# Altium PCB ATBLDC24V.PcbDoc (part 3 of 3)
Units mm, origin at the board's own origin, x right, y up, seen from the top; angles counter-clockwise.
Board outline 135 x 125 mm, 4 copper layers (Top Layer, GND, PWR/Signal, Bottom Layer), stack 1.716 mm thick; 340 components, 168 nets, 921 pads, 872 vias.
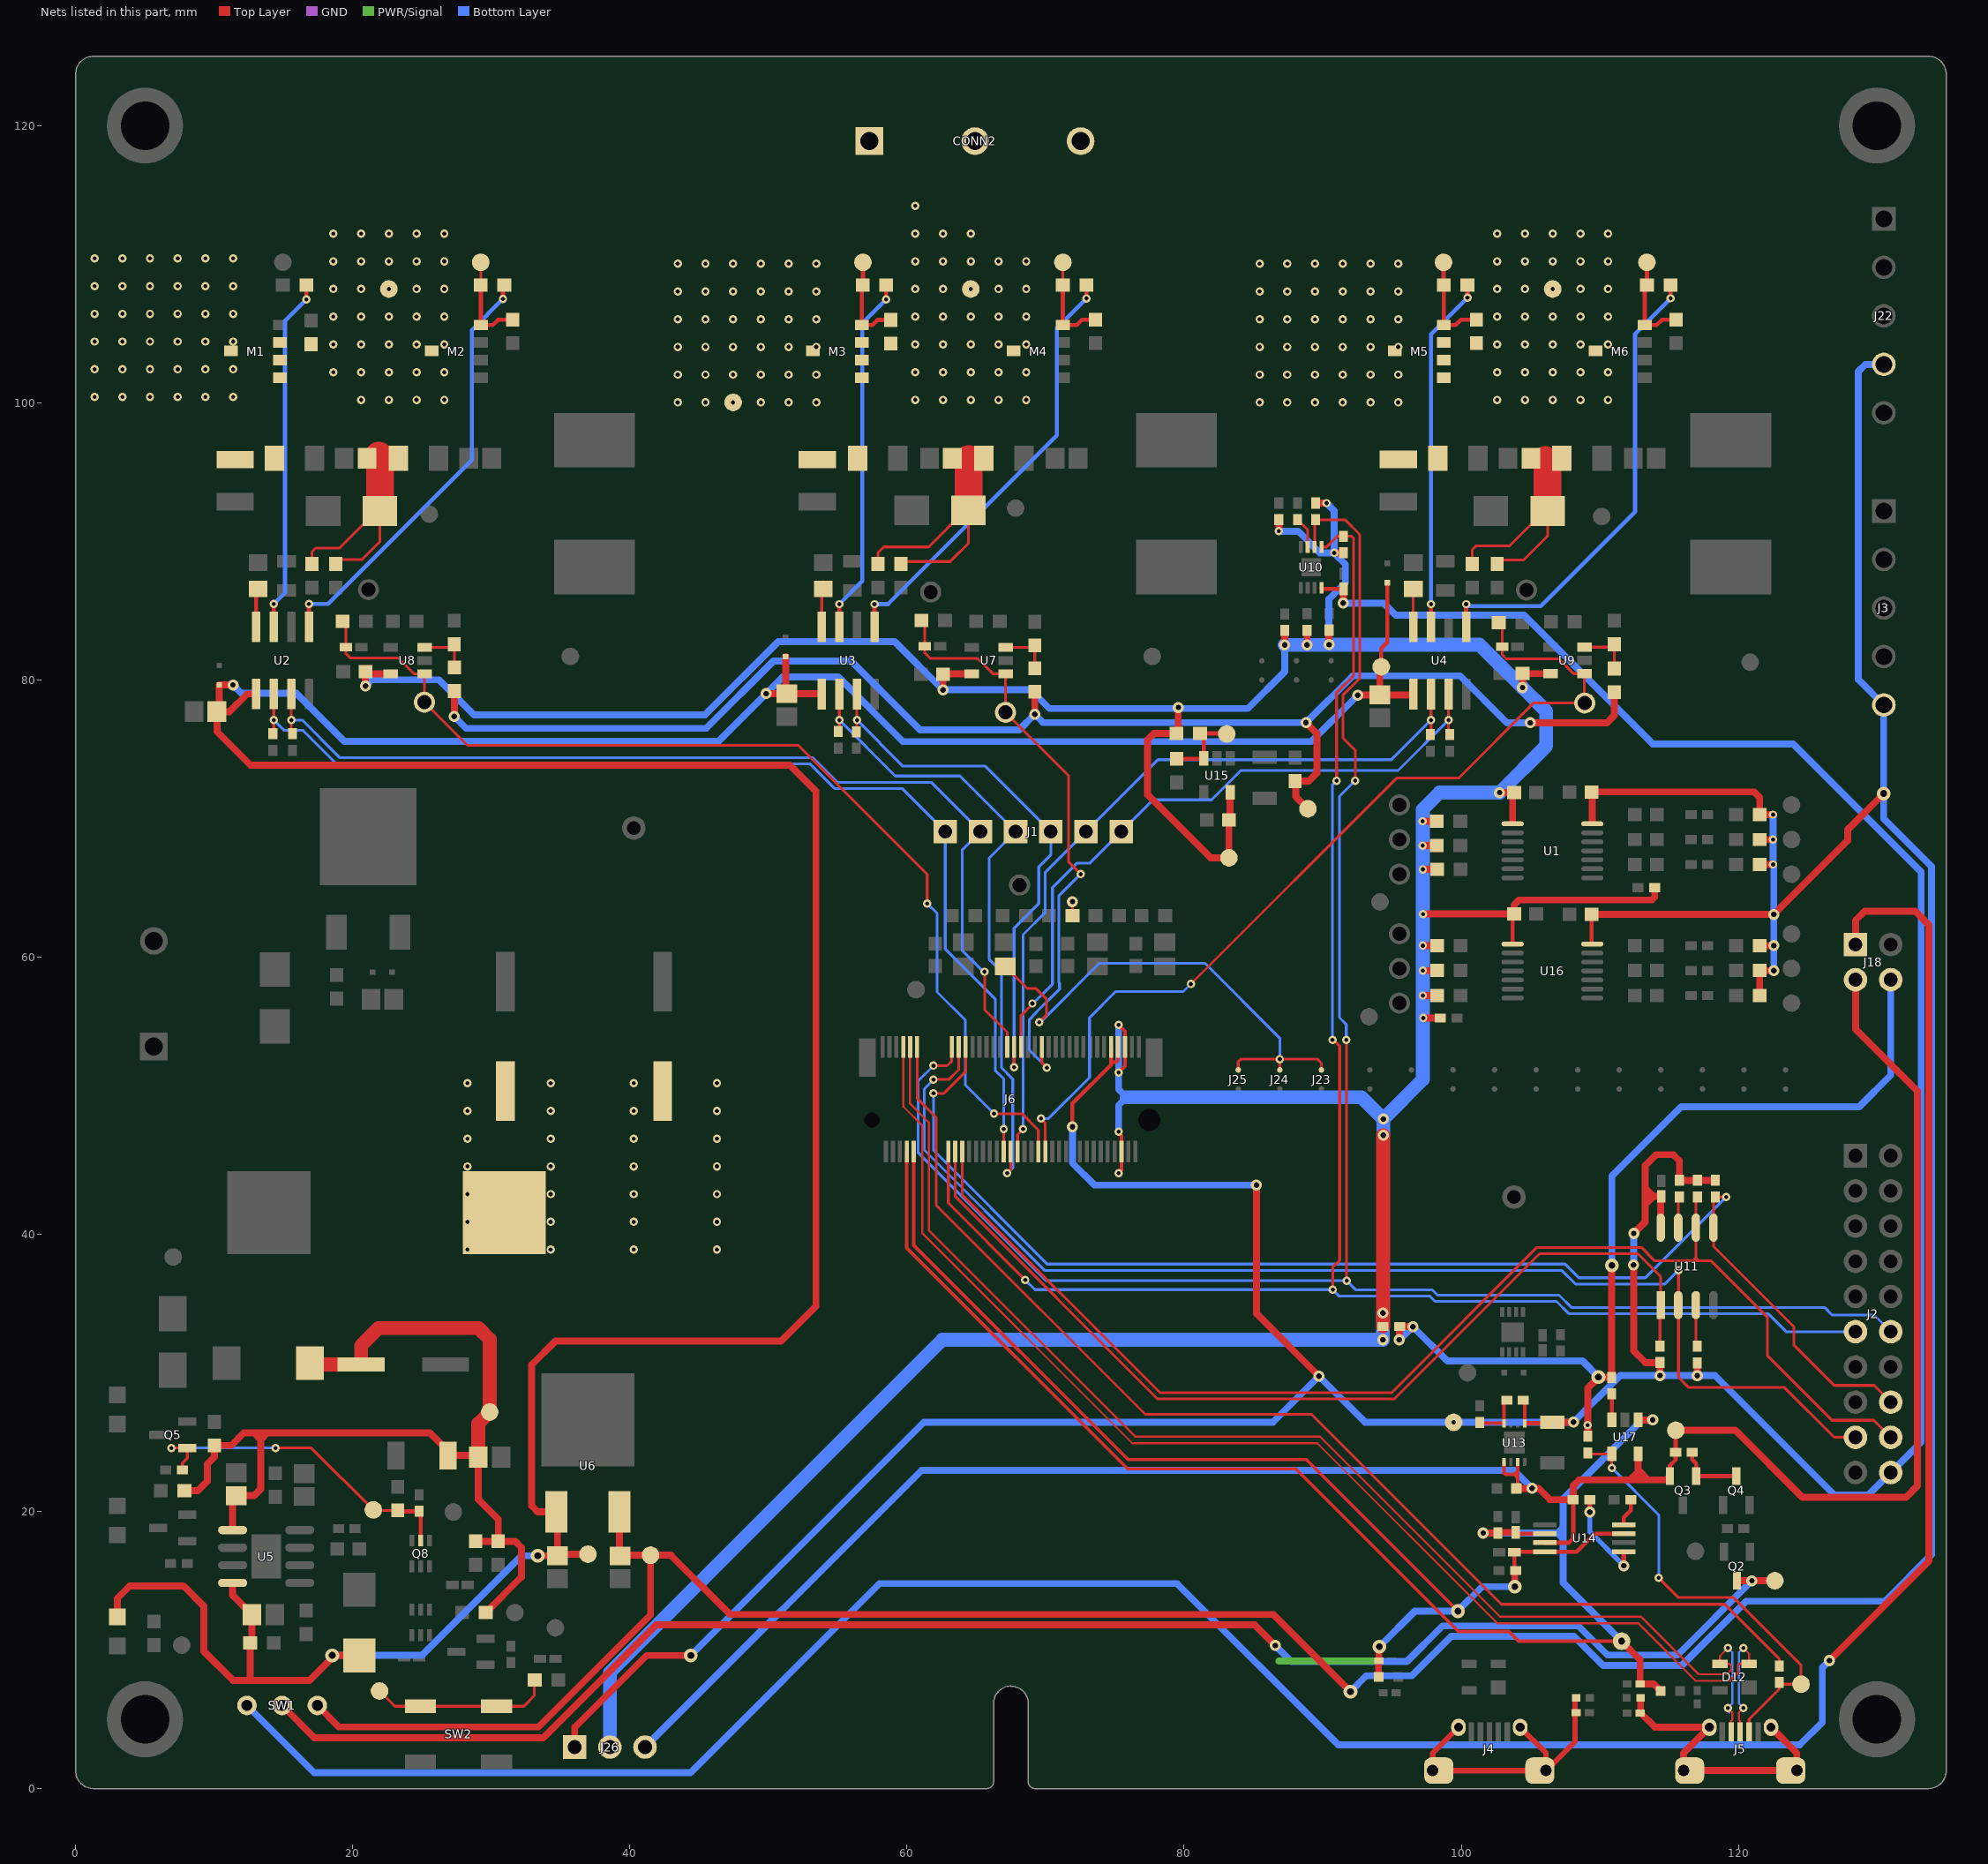
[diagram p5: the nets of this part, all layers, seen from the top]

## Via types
v1: diameter 0.6, hole 0.3, Top Layer to Bottom Layer, 769 vias
v2: diameter 0.8, hole 0.4, Top Layer to Bottom Layer, 92 vias
v3: diameter 1, hole 0.5, Top Layer to Bottom Layer, 11 vias

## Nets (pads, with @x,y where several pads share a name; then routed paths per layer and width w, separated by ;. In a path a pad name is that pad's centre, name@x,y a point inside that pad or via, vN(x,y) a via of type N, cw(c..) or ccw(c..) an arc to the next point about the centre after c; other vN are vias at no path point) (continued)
NetM2_2: M2.2 R11.2 R57.1 TP51.1 | length 7.1
  Top Layer w0.2: R57.1@29.235,108.5 TP51.1@29.235,110.135
  Top Layer w0.3: R57.1@29.55,108.5 29.25,108.2 M2.2@29.25,105.615 30.105,105.615 30.49,106 R11.2@31.55,106
NetM3_2: M3.2 R10.2 R17.2 TP8.1 | length 6.8
  Top Layer w0.3: TP8.1@56.8,110.087 56.817,110.103 56.817,108.517 R10.2@56.8,108.5 56.75,108.45 M3.2@56.75,105.615 57.519,105.615 57.884,105.98 R17.2@58.835,105.98
NetM4_2: M4.2 R21.2 R47.1 TP48.1 | length 7
  Top Layer w0.2: R47.1@71.25,108.5 TP48.1@71.25,110.135
  Top Layer w0.3: R47.1@71.25,108.5 M4.2@71.25,105.615 72.242,105.615 72.627,106 R21.2@73.6,106
NetM5_2: M5.2 R27.2 R58.2 TP9.1 | length 6.9
  Top Layer w0.3: TP9.1@98.724,110.017 98.724,108.526 R58.2@98.75,108.5 M5.2@98.75,105.615 99.593,105.615 99.978,106 R27.2@101.1,106
NetM6_2: M6.2 R31.2 R59.1 TP56.1 | length 7
  Top Layer w0.3: TP56.1@113.4,110.135 R59.1@113.4,108.5 113.25,108.35 M6.2@113.25,105.615 114.105,105.615 114.49,106 R31.2@115.5,106
NetQ3_1: Q3.1 Q4.3 R97.1 | length 4.7
  Top Layer w0.3: R97.1@116.675,24.267 116.675,23.756 116.962,23.469 Q3.1@116.962,22.549 119.849,22.549 Q4.3@119.85,22.55
NetQ5_1: Q5.1 Q8.5 R66.2 R117.1 R118.2 TP41.1 | length 24.8
  Top Layer w0.2: v1(6.904,24.579) Q5.1@8.05,24.579 8.05,23.84 7.7,23.49 R66.2@7.7,23 ; v1(14.416,24.579) 17.012,24.579 TP41.1@21.481,20.11 21.516,20.075 R117.1@23.243,20.075 R117.1@23.313,20.005
  Top Layer w0.3: R117.1@23.313,20.005 R118.2@24.797,20.005 24.9,19.901 Q8.5@24.9,17.896
  Bottom Layer w0.2: v1(6.904,24.579) v1(14.416,24.579)
NetR5_1: R5.1 U2.8 | length 2.7
  Top Layer w0.3: U2.8@13.023,83.837 R5.1@13.023,86.028 ; R5.1@13.165,86.593 R5.1@13.538,86.22
NetR10_1: R10.1 U3.7 | length 26.1
  Top Layer w0.3: U3.7@55.115,83.825 v1(55.115,85.47) ; v1(58.5,107.463) R10.1@58.5,108.5
  Bottom Layer w0.3: v1(55.115,85.47) 56.774,87.129 56.774,105.737 v1(58.5,107.463)
NetR15_1: R15.1 U3.8 | length 3.1
  Top Layer w0.2: U3.8@53.845,83.825 R15.1@53.845,86.794 ; R15.1@53.867,86.999 R15.1@53.95,87.081
NetR20_1: R20.1 U2.7 | length 25.6
  Top Layer w0.3: U2.7@14.293,83.837 v1(14.293,85.481) ; v1(16.65,107.462) R20.1@16.65,108.5
  Bottom Layer w0.3: v1(14.293,85.481) 15.11,86.299 15.11,105.922 v1(16.65,107.462)
NetR25_1: R25.1 U4.8 | length 2.7
  Top Layer w0.2: R25.1@96.539,86.527 96.539,83.831 U4.8@96.545,83.825
NetR39_2: R39.2 R44.2 U7.3 | length 3.8
  Top Layer w0.2: U7.3@67.125,82.353 69.083,82.353 R39.2@69.221,82.492 R44.2@69.221,80.842
NetR41_2: R41.2 R45.2 U8.3 | length 3.6
  Top Layer w0.2: U8.3@25.175,82.353 26.995,82.353 R41.2@27.06,82.418 ; R41.2@27.317,82.573 27.337,82.553 R45.2@27.337,80.898
NetR47_2: R47.2 U3.5 | length 31.6
  Top Layer w0.3: U3.5@57.655,83.825 v1(57.655,85.47) ; v1(72.95,107.532) R47.2@72.95,108.5
  Bottom Layer w0.3: v1(57.655,85.47) 58.634,85.47 70.819,97.654 70.819,105.401 v1(72.95,107.532)
NetR49_2: R49.2 R50.2 U9.3 | length 4
  Top Layer w0.2: U9.3@108.886,82.362 110.835,82.362 R49.2@111.043,82.569 111.052,82.56 R50.2@111.052,80.817
NetR54_1: R54.1 R56.2 TP61.1 U15.3 | length 5.8
  Top Layer w0.3: R56.2@79.473,74.309 81.393,74.309 U15.3@81.418,74.333 81.418,75.997 R54.1@81.276,76.139 ; R54.1@81.145,76.147 83.03,76.147 TP61.1@83.077,76.1
NetR57_2: R57.2 U2.5 | length 31.3
  Top Layer w0.3: U2.5@16.833,83.837 v1(16.833,85.481) ; v1(30.835,107.481) 30.835,108.4 R57.2@30.935,108.5
  Bottom Layer w0.3: v1(16.833,85.481) 18.2,85.481 28.592,95.872 28.592,105.238 v1(30.835,107.481)
NetR58_1: R58.1 U4.7 | length 25.8
  Top Layer w0.3: U4.7@97.815,83.825 v1(97.815,85.47) ; v1(100.45,107.581) R58.1@100.45,108.5
  Bottom Layer w0.3: v1(97.815,85.47) 97.815,104.946 v1(100.45,107.581)
NetR59_2: R59.2 U4.5 | length 34.1
  Top Layer w0.3: U4.5@100.355,83.825 v1(100.355,85.47) ; v1(115.1,107.536) R59.2@115.1,108.5
  Bottom Layer w0.3: v1(100.355,85.47) 100.494,85.33 105.741,85.33 112.546,92.136 112.546,104.982 v1(115.1,107.536)
NetR87_1: R87.1 U10.3 | length 2.3
  Top Layer w0.2: R87.1@88.187,91.562 88.917,90.833 U10.3@88.917,89.597
NetR89_2: R89.2 U11.3 | length 3
  Top Layer w0.2: U11.3@116.935,34.89 116.935,32.03 R89.2@117.035,31.93
NetR92_1: R92.1 U11.7 | length 2.2
  Top Layer w0.2: U11.7@115.665,40.478 115.665,42.61 R92.1@115.745,42.69
NetR94_1: R94.1 R96.2 U13.8 | length 3.5
  Top Layer w0.25: R94.1@101.334,26.417 101.384,26.367 U13.8@103.084,26.367 103.084,27.817 R96.2@103.284,28.017
NetR95_1: R95.1 U14.1 | length 6.8
  Top Layer w0.35: v2(109.284,19.945) R95.1@109.284,20.842 ; v2(111.734,16.083) U14.1@111.734,17.092
  Bottom Layer w0.35: v2(109.284,19.945) 109.284,18.533 v2(111.734,16.083)
NetR100_2: R100.2 U14.4 | length 2
  Top Layer w0.3: U14.4@111.734,19.042 111.734,19.567 112.234,20.067 R100.2@112.234,20.842
NetR102_2: R102.2 U17.3 | length 1.9
  Top Layer w0.3: R102.2@110.867,28.479 110.867,26.603 U17.3@110.869,26.601
NetR122_1: R122.1 SW2.1 SW2.2 TP44.1 | length 13.1
  Top Layer w0.2: TP44.1@21.93,7.046 23.035,5.941 SW2.1@24.885,5.941 SW2.2@30.385,5.941 32.34,5.941 33.1,6.701 33.1,7.81 R122.1@33.133,7.842
PA03_USB_ID: J6.11 R43.2 | length 86.9
  Top Layer w0.2: J6.11@60.73,53.525 60.73,49.813 62.111,48.432 62.111,42.093 77.199,27.005 89.191,27.005 102.901,13.296 119.026,13.296 122.95,9.371 R43.2@122.95,8.85
PWM_UH: J1.6 J6.28 R3.2 U2.2 | length 79.6
  Top Layer w0.2: R3.2@14.159,76.192 R3.2@14.226,76.125 14.293,76.192 v1(14.293,77.1) U2.2@14.293,78.987 ; J6.28@66.98,45.975 v1(66.98,47.586)
  Bottom Layer w0.2: v1(14.293,77.1) 15.023,76.37 16.384,76.37 18.804,73.95 52.991,73.95 54.775,72.166 59.642,72.166 J1.6@62.757,69.05 62.757,60.59 66.367,56.981 66.367,51.827 66.98,51.213 v1(66.98,47.586)
PWM_UL: J1.5 J6.29 R4.1 U2.3 | length 73.7
  Top Layer w0.2: U2.3@15.563,78.987 v1(15.563,77.1) 15.563,76.178 15.646,76.095 R4.1@15.743,76.192 ; v1(65.603,58.948) 65.603,56.208 67.23,54.58 J6.29@67.23,53.525
  Bottom Layer w0.2: v1(15.563,77.1) 16.347,77.1 19.047,74.4 53.177,74.4 54.961,72.616 61.732,72.616 J1.5@65.297,69.05 63.993,67.746 63.993,60.466 65.603,58.856 v1(65.603,58.948)
PWM_VH: J1.4 J6.30 R13.2 U3.2 | length 46.9
  Top Layer w0.2: R13.2@54.974,76.342 R13.2@55.035,76.281 55.115,76.361 v1(55.115,77.1) U3.2@55.115,78.975 ; v1(67.23,44.4) 67.48,44.651 J6.30@67.48,45.975
  Bottom Layer w0.2: v1(55.115,77.1) 59.15,73.066 63.822,73.066 J1.4@67.837,69.05 65.918,67.131 65.918,59.859 66.817,58.961 66.817,52.013 67.63,51.199 67.63,44.801 v1(67.23,44.4) ; v1@55.115,77.208 v1@55.169,77.154
PWM_VL: J1.3 J6.31 R14.1 U3.3 | length 39.7
  Top Layer w0.2: R14.1@56.343,76.263 R14.1@56.385,76.305 ; U3.3@56.385,78.975 v1(56.385,77.1) R14.1@56.385,76.305 ; R14.1@56.422,76.342 R14.1@56.385,76.305 ; v1@67.73,52.072 J6.31@67.73,53.525
  Bottom Layer w0.2: v1(56.385,77.1) 59.707,73.778 65.65,73.778 J1.3@70.377,69.05 70.377,67.375 69.511,66.509 69.511,63.872 67.73,62.091 v1(67.73,52.05)
PWM_WH: J1.2 J6.32 R23.2 U4.2 | length 56.5
  Top Layer w0.2: J6.32@67.98,45.975 67.98,47.192 68.377,47.589 v1(68.377,47.597) ; R23.2@97.689,76.142 R23.2@97.775,76.056 97.815,76.095 U4.2@97.815,78.975
  Bottom Layer w0.2: v1(68.377,47.597) 68.377,47.647 v1@68.38,47.65 ; v1@68.38,47.586 v1@68.38,47.65 ; v1(97.812,77.1) 94.961,74.25 78.117,74.25 J1.2@72.917,69.05 69.961,66.094 69.961,63.201 68.38,61.621 v1@68.38,47.65
PWM_WL: J1.1 J6.33 R24.1 U4.3 | length 49.1
  Top Layer w0.2: J6.33@68.23,53.525 68.23,55.78 69.05,56.6 v1(69.05,56.65) ; U4.3@99.085,78.975 v1(99.085,77.1) 99.085,76.146 R24.1@99.175,76.056 R24.1@99.262,76.142
  Bottom Layer w0.2: v1(69.05,56.65) 69.1,56.65 70.499,58.049 70.499,65.018 72.254,66.773 73.18,66.773 J1.1@75.457,69.05 77.757,71.35 81.98,71.35 84.092,73.462 95.447,73.462 v1(99.085,77.1)
REF_BEMF_SENS: J23.1 J24.1 J25.1 L5.2 | length 36.7
  Top Layer w0.2: L5.2@67.1,59.325 68.695,57.73 69.319,57.73 70.056,56.993 70.056,55.807 v1(69.55,55.3) ; J25.1@83.907,51.862 83.907,52.458 84.083,52.634 v1(86.907,52.634) ; J24.1@86.907,51.862 v1(86.907,52.634) ; J23.1@89.907,51.862 89.907,52.355 89.628,52.634 v1(86.907,52.634)
  Bottom Layer w0.2: v1(69.55,55.3) 69.628,55.3 73.881,59.553 81.505,59.553 86.907,54.151 v1(86.907,52.634)
SHIELD: C29.2 J4.6@97.943,1.3 J4.7@106.118,1.3 J4.8@99.805,4.425 J4.9@104.255,4.425 R37.2 | length 22.1
  Top Layer w0.4: J4.8@99.805,4.425 97.943,2.563 J4.6@97.943,1.3 J4.7@106.118,1.3 ; J4.9@104.255,4.425 106.118,2.563 J4.7@106.118,1.3 ; R37.2@108.22,6.547 108.22,3.402 J4.7@106.118,1.3
SPI_MISO: J2.17@128.46,25.349 J6.15 U11.2 | length 90.4
  Top Layer w0.2: v1@61.807,51.123 v1@61.912,51.123 ; v1(61.912,51.166) 63.021,51.166 63.73,51.876 J6.15@63.73,53.525 ; v1(115.68,37.4) 115.68,29.686 116.423,28.943 123.321,28.943 126.916,25.349 J2.17@128.46,25.349
  Bottom Layer w0.2: v1(61.912,51.166) 61.245,50.5 61.245,46.084 69.931,37.397 80.285,37.397 ; 80.285,37.397 81.569,37.397 ; 81.569,37.397 107.255,37.397 108.243,36.409 114.689,36.409 v1(115.68,37.4)
SPI_MOSI: J2.16@131,27.889 J6.17 R90.2 U11.5 | length 94.9
  Top Layer w0.2: v1(61.912,50.166) 62.658,50.166 64.23,51.739 J6.17@64.23,53.525 ; v1(119.12,42.69) R90.2@118.345,42.69 118.205,42.55 U11.5@118.205,40.478 118.205,39.14 124.003,33.342 124.003,32.014 126.928,29.089 129.8,29.089 J2.16@131,27.889
  Bottom Layer w0.2: v1(61.912,50.166) 61.912,46.053 70.118,37.847 80.471,37.847 ; 80.471,37.847 81.383,37.847 ; 81.383,37.847 107.488,37.847 108.477,36.859 113.288,36.859 v1(119.12,42.69)
SPI_SCK: J2.18@131,25.349 J6.16 R91.2 U11.6 | length 94.7
  Top Layer w0.2: J6.16@63.98,45.975 63.98,42.856 78.266,28.571 94.988,28.571 105.467,39.05 113.007,39.05 113.974,38.083 116.727,38.083 ; U11.6@116.95,39.721 U11.6@116.95,41.148 ; R91.2@117.045,42.69 116.935,42.58 U11.6@116.935,40.478 116.935,38.291 ; 117.491,38.083 117.143,38.083 ; J2.18@131,25.349 129.769,26.58 126.757,26.58 122.089,31.249 122.089,34.038 118.044,38.083 117.143,38.083 ; 116.727,38.083 116.938,38.083 ; 116.727,38.083 116.935,38.291 ; 116.935,38.291 117.143,38.083 ; 116.935,38.291 116.935,38.086 116.938,38.083 ; 116.938,38.083 117.143,38.083
SPI_SS: J6.14 R88.2 U11.1 | length 70.3
  Top Layer w0.2: J6.14@63.48,45.975 63.48,42.72 78.08,28.121 95.18,28.121 105.659,38.6 112.747,38.6 114.395,36.952 U11.1@114.395,34.89 114.345,34.84 R88.2@114.345,31.94 R88.2@114.365,31.94
TARGET_USB_HS_N: D12.3 J5.2 J6.9 | length 93.9
  Top Layer w0.15: J6.9@60.23,53.525 60.22,53.515 60.22,49.42 61.574,48.066 61.574,40.292 76.459,25.407 89.798,25.407 102.789,12.416 112.966,12.416 117.128,8.254 119.184,8.254 119.485,8.555 119.485,8.877 119.364,8.998 D12.3@119.02,8.998 ; D12.3@118.675,8.997 118.675,9.577 v1(119.246,10.148) ; v1(119.246,5.822) 119.565,5.503 119.565,4.941 119.48,4.856 J5.2@119.48,4.1
  GND w0.15: 119.34,5.493 v1@119.34,5.624
  Bottom Layer w0.15: v1(119.246,5.822) 119.565,6.142 119.565,9.828 v1(119.246,10.148)
TARGET_USB_HS_P: D12.2 J5.3 J6.7 | length 95.7
  Top Layer w0.15: J6.7@59.73,53.525 59.73,53.091 59.74,53.081 59.74,49.221 61.094,47.867 61.094,40.093 76.26,24.927 89.599,24.927 102.59,11.936 112.767,11.936 116.929,7.774 119.383,7.774 119.965,8.356 119.965,8.877 120.086,8.998 120.775,8.998 120.775,9.738 v1(120.365,10.148) ; J5.3@120.13,4.1 120.13,4.856 120.045,4.941 120.045,5.503 v1(120.365,5.822)
  Bottom Layer w0.15: v1(120.365,5.822) 120.045,6.142 120.045,9.828 v1(120.365,10.148)
TARGET_USB_ID: J5.4 R43.1 R104.1 TP68.1 U17.4 | length 32.4
  Top Layer w0.2: R104.1@109.131,24.228 109.209,24.151 U17.4@110.869,24.151 v1(110.869,23.136) ; v1(114.255,15.217) 115.684,13.787 119.653,13.787 124.525,8.916 TP68.1@124.525,7.531 R43.1@122.95,7.531 ; J5.4@120.78,4.1 120.78,5 122.95,7.17 R43.1@122.95,7.531 ; R43.1@122.95,7.65 R43.1@122.95,7.531
  Bottom Layer w0.2: v1(110.869,23.136) 114.255,19.751 v1(114.255,15.217)
TARGET_USB_SHIELD: C32.2 J5.6@116.043,1.3 J5.7@124.218,1.3 J5.8@117.905,4.425 J5.9@122.355,4.425 R42.2 | length 22.4
  Top Layer w0.5: R42.2@112.939,6.547 112.939,5.472 113.986,4.425 J5.8@117.905,4.425 116.043,2.563 J5.6@116.043,1.3 J5.7@124.218,1.3 124.218,2.563 J5.9@122.355,4.425
TWI_SCL: J2.12@131,32.969 J6.13 R84.2 U10.2 | length 145.8
  Top Layer w0.2: v1(61.912,52.166) 62.905,52.166 63.23,52.492 J6.13@63.23,53.525 ; U10.2@89.417,89.597 89.417,91.492 R84.2@89.487,91.562 91.615,91.562 92.677,90.5 92.677,80.112 91.458,78.892 91.458,75.818 92.35,74.926 v1(92.35,72.73) ; v1(91.707,54.023) 91.727,54.003 v1(91.727,36.65)
  Bottom Layer w0.2: v1(61.912,52.166) 60.795,51.05 60.795,45.897 70.043,36.65 v1(91.727,36.65) 92.395,35.982 97.929,35.982 98.302,35.608 107.064,35.608 107.949,34.724 126.213,34.724 126.768,34.169 129.8,34.169 J2.12@131,32.969 ; v1(91.707,54.023) 91.707,55.135 91.211,55.631 91.211,71.591 v1(92.35,72.73)
TWI_SDA: J2.11@128.46,32.969 J6.12 R83.2 U10.1 | length 131.1
  Top Layer w0.2: J6.12@62.98,45.975 62.98,42.26 v1(68.532,36.708) ; U10.1@89.917,89.597 90.28,89.597 91.05,90.368 R83.2@91.494,90.368 92.088,90.368 92.227,90.228 92.227,80.302 91,79.075 v1(91,72.73) ; v1(90.707,54.023) 90.788,54.023 91.223,53.588 91.223,38.114 90.727,37.618 v1(90.727,36)
  Bottom Layer w0.2: v1(68.532,36.708) 69.241,36 v1(90.727,36) 91.195,35.532 97.742,35.532 98.116,35.158 106.878,35.158 107.762,34.274 122.141,34.274 123.446,32.969 J2.11@128.46,32.969 ; v1(90.707,54.023) 90.707,72.437 v1(91,72.73)
U_EMF: C6.2 CONN2.1 D2.1 M1.1 M2.3 R7.1 R8.2 R9.2 R64.1 TP47.1 | length 17.5
  Top Layer w0.2: R8.2@17.049,88.403 17.049,89.236 17.328,89.516 19.036,89.516 21.709,92.188 D2.1@21.957,92.188 21.957,89.972 20.678,88.692 19.09,88.692 R64.1@18.962,88.564 ; R64.1@18.54,88.564 R64.1@18.962,88.564 ; R64.1@18.765,88.368 R64.1@18.962,88.564
  Top Layer w2: 21.884,96.191 21.957,96.117 D2.1@21.957,92.188
  other v1: 20.6,100.208 22.6,100.208 24.6,100.208 26.6,100.208 18.6,102.208 20.6,102.208 22.6,102.208 24.6,102.208 26.6,102.208 18.6,104.208 20.6,104.208 22.6,104.208 24.6,104.208 26.6,104.208 18.6,106.208 20.6,106.208 22.6,106.208 24.6,106.208 26.6,106.208 18.6,108.208 20.6,108.208 22.6,108.208 24.6,108.208 26.6,108.208 18.6,110.208 20.6,110.208 22.6,110.208 24.6,110.208 26.6,110.208 18.6,112.208 20.6,112.208 22.6,112.208 24.6,112.208 26.6,112.208
USHUNT_ADC: C34.2 J6.38 R52.2 TP13.1 U8.1 | length 76.7
  Top Layer w0.2: R52.2@19.259,84.233 19.51,83.983 C34.2@19.51,82.358 19.51,81.882 19.802,81.59 23.261,81.59 24.403,80.447 U8.1@25.175,80.447 25.175,78.398 TP13.1@25.168,78.39 28.277,75.281 52.155,75.281 61.456,65.981 v1@61.456,63.858 ; v1(66.277,48.7) 68.297,48.7 69.48,47.516 J6.38@69.48,45.975
  Bottom Layer w0.2: v1(61.457,63.87) 62.172,63.155 62.172,57.484 64.215,55.441 64.215,50.762 v1(66.277,48.7)
V_EMF: C11.2 CONN2.2 D4.1 M3.1 M4.3 R17.1 R18.2 R19.2 R68.1 TP46.1 | length 20.2
  Top Layer w0.2: R18.2@57.9,88.368 57.9,89.174 58.319,89.593 61.563,89.593 64.202,92.231 D4.1@64.435,92.231 64.435,89.86 63.118,88.542 59.724,88.542 R68.1@59.55,88.368
  Top Layer w2: D4.1@64.435,92.231 64.435,95.922 64.446,95.933
  other v1: 60.6,100.208 62.6,100.208 64.6,100.208 66.6,100.208 68.6,100.208 60.6,102.208 62.6,102.208 64.6,102.208 66.6,102.208 68.6,102.208 60.6,104.208 62.6,104.208 64.6,104.208 66.6,104.208 68.6,104.208 60.6,106.208 62.6,106.208 64.6,106.208 66.6,106.208 68.6,106.208 60.6,108.208 62.6,108.208 64.6,108.208 66.6,108.208 68.6,108.208 60.6,110.208 62.6,110.208 64.6,110.208 66.6,110.208 68.6,110.208 60.6,112.208 62.6,112.208 64.6,112.208 60.6,114.208
VCC_D: C4.1 C9.1 C14.1 C19.1 C22.1 C27.1 D1.2 D3.2 D5.2 D11.2 R32.2 TP10.1 TP39.1 U2.1 U3.1 U4.1 U5.8 U6.1 | length 288.2
  Top Layer w0.3: TP39.1@94.127,80.85 TP39.1@94.127,80.95 ; TP39.1@94.227,80.95 94.227,82.265 94.671,82.709 D5.2@94.671,87.009
  Top Layer w0.5: D11.2@3,12.4 3,13.722 3.908,14.63 7.689,14.63 7.719,14.6 7.812,14.6 9.254,13.158 9.254,9.909 11.361,7.802 12.482,7.802 ; U5.8@11.325,14.845 11.325,13.95 C19.1@12.725,12.55 12.725,10.661 R32.2@12.586,10.522 12.586,7.907 12.482,7.802 ; v2(11.354,79.638) D1.2@10.357,79.638 10.357,77.874 C4.1@10.192,77.709 ; U2.1@13.023,78.987 12.379,78.987 11.101,77.709 C4.1@10.192,77.709 ; v3@18.599,9.529 16.872,7.802 12.482,7.802 ; v3@18.68,9.61 C22.1@20.47,9.61 ; v3(33.35,16.801) C27.1@34.767,16.801 ; TP10.1@36.973,16.918 34.883,16.918 C27.1@34.767,16.801 ; v2(49.829,79.008) C9.1@51.338,79.008 ; D3.2@51.238,81.683 51.238,79.108 C9.1@51.338,79.008 ; U3.1@53.845,78.975 53.812,79.008 C9.1@51.338,79.008 ; v2(92.527,78.9) C14.1@93.845,78.9 ; C14.1@94.127,78.9 96.47,78.9 U4.1@96.545,78.975 ; C14.1@94.127,78.925 TP39.1@94.127,80.85 ; C4.1@10.192,77.709 10.192,76.28 12.617,73.856 51.541,73.856 53.427,71.97 53.427,34.812 50.912,32.297 34.622,32.297 32.917,30.593 32.917,20.396 33.351,19.962 U6.1@34.689,19.962 34.767,19.884 C27.1@34.767,16.801
  Bottom Layer w0.5: v2(11.354,79.638) 11.962,79.03 15.933,79.03 19.393,75.57 46.39,75.57 v2(49.829,79.008) 51.032,80.212 55.047,80.212 59.708,75.55 89.177,75.55 v2(92.527,78.9) ; v3(18.517,9.61) 24.981,9.61 32.172,16.801 v3(33.35,16.801)
VCC_D_P5V0: C1.1 C28.1 C44.1 J3.5 J22.4 R67.2 R70.2 R72.2 R109.2 R110.2 R111.2 SW1.2 TP11.1 U1.14 U6.3 U16.14 | length 290.8
  Top Layer w0.3: C44.1@109.416,63.081 109.416,60.99 U16.14@109.461,60.946
  Top Layer w0.5: SW1.2@17.44,6 18.992,4.448 33.396,4.448 41.49,12.543 TP11.1@41.49,16.842 ; U6.3@39.249,19.962 39.249,16.824 39.267,16.842 TP11.1@41.49,16.842 ; v3(92.002,6.995) 86.433,12.564 47.236,12.564 42.958,16.842 TP11.1@41.49,16.842 ; C44.1@109.416,63.081 v2(122.563,63.081) 127.892,68.41 127.892,69.202 v3(130.49,71.8) ; U1.14@109.461,69.756 109.461,71.873 C1.1@109.416,71.918 121.141,71.918 121.538,71.52 R67.2@121.538,70.281 v1(122.506,70.281) ; R111.2@121.538,57.228 R110.2@121.538,59.028 v2(122.562,59.028) ; R109.2@121.538,60.828 v2(122.562,60.828) ; R72.2@121.538,66.681 v1(122.506,66.681) ; R70.2@121.538,68.481 v1(122.506,68.481)
  Bottom Layer w0.5: v3(92.002,6.995) 93.145,8.138 96.432,8.138 99.28,10.986 108.139,10.986 110.242,8.884 115.923,8.884 120.564,13.524 130.592,13.524 133.949,16.881 133.949,66.54 130.49,69.999 v3(130.49,71.8) J3.5@130.49,78.199 ; v1(122.506,70.281) v1(122.506,68.481) v1(122.506,66.681) 122.562,66.625 v2@122.562,63.1 ; v2(122.562,59.028) v2(122.562,60.828) v2(122.563,63.081) v2@122.582,63.1 ; J3.5@130.5,78.19 J3.5@130.49,78.199 ; J22.4@130.5,102.77 129.176,102.77 128.654,102.248 128.654,80.036 J3.5@130.49,78.199
VCC_EDBG_USB_P5V0: C31.1 C65.1 J6.10 L1.2 R98.2 U14.3 U14.8 | length 81.7
  Top Layer w0.25: J6.10@60.48,45.975 60.48,39.215 75.953,23.742 88.817,23.742 v3(99.759,12.799)
  Top Layer w0.3: R98.2@103.834,15.734 C65.1@103.834,17.067 103.859,17.092 U14.8@106.034,17.092 108.326,17.092 109.626,18.392 U14.3@111.734,18.392
  Top Layer w0.5: L1.2@94.032,8.073 94.032,9.198 C31.1@94.057,9.223 94.057,10.204 v3(94.094,10.241) ; R98.2@103.834,15.734 103.867,15.701 v3(103.867,14.576)
  Bottom Layer w0.5: v3(94.094,10.241) 96.652,12.799 v3@99.732,12.799 ; v3(99.759,12.799) v3@99.732,12.799 ; v3(103.867,14.576) 101.509,14.576 v3@99.732,12.799
VCC_EXT_P5V0: Q2.3 SW1.1 TP63.1 | length 118.4
  Top Layer w0.5: SW1.1@14.9,6 17.244,3.657 33.736,3.657 41.893,11.814 85.089,11.814 v2(86.577,10.326) ; Q2.3@119.9,15 v2(120.977,15) TP63.1@122.639,15
  Bottom Layer w0.5: v2(86.577,10.326) 87.732,9.171 96.085,9.171 98.65,11.736 108.45,11.736 110.552,9.634 115.61,9.634 v2(120.977,15)
VCC_P: C2.1 C35.1 C36.1 C38.1 C39.2 C45.1 J6.62 J6.63 J26.2@38.55,2.997 R1.2 R54.2 R60.2 R61.2 R63.2 R81.1 R82.1 R83.1 R84.1 R85.1 R86.1 R105.2 R106.2 R107.2 R108.2 R112.2 TP20.1 U1.1 U7.5 U8.5 U9.5 U15.5 U16.1 | length 343.9
  Top Layer w0.25: v1@75.226,47.35 75.48,47.096 J6.62@75.48,45.975 75.48,44.605 v1(75.275,44.4) ; v1(75.275,51.672) 75.73,52.127 J6.63@75.73,53.525 75.73,54.646 v1(75.275,55.101)
  Top Layer w0.3: U16.1@103.711,60.946 103.711,63.002 C45.1@103.816,63.108
  Top Layer w0.5: v2(20.91,79.571) C36.1@20.91,80.608 21.071,80.447 U8.5@22.725,80.447 ; v2(62.6,79.284) C35.1@62.6,80.4 62.647,80.447 U7.5@64.675,80.447 ; v2(79.585,78.012) 79.576,78.003 79.576,76.139 77.822,76.139 77.36,75.677 77.36,71.723 81.921,67.162 TP20.1@83.235,67.162 C39.2@83.235,69.912 83.324,70.001 U15.5@83.324,71.883 ; v1(86.837,90.731) R86.1@86.837,91.562 ; v2@87.257,82.621 R82.1@87.257,83.566 ; v2(88.867,82.528) R85.1@88.867,83.472 ; R84.1@89.487,92.762 v1(90.281,92.762) ; v2(90.457,82.546) R81.1@90.457,83.491 ; v1(90.833,89.168) R83.1@91.494,89.168 ; v1(97.208,69.806) R60.2@98.232,69.806 ; v1(97.216,68.048) R61.2@98.239,68.048 ; v1(97.232,57.227) R108.2@98.255,57.227 ; v1(97.232,59.027) R107.2@98.255,59.027 ; v1(97.232,60.827) R106.2@98.255,60.827 ; v1(97.232,66.329) R63.2@98.255,66.329 ; v1(97.238,63.108) C45.1@103.816,63.108 103.816,63.761 104.176,64.122 113.746,64.122 113.961,64.337 R1.2@113.961,65.014 ; v1(97.259,55.606) 97.265,55.6 R112.2@98.5,55.6 ; v2(102.766,71.868) C2.1@103.711,71.868 ; U1.1@103.711,69.742 C2.1@103.711,71.868 ; C2.1@103.816,71.868 C2.1@103.711,71.868 ; v2(104.421,79.453) C38.1@104.421,80.466 104.431,80.456 U9.5@106.436,80.456
  Top Layer w1: R105.2@94.366,33.353 v2@94.366,47.15
  PWR/Signal w0.5: 86.837,9.198 94.032,9.198
  Bottom Layer w0.5: v2(20.91,79.571) 21.348,80.01 26.217,80.01 28.752,77.475 45.415,77.475 50.705,82.766 59.118,82.766 v2(62.6,79.284) 68.937,79.284 70.283,77.937 v2@79.585,77.937 ; v1(75.275,47.4) 75.275,49.316 75.848,49.889 75.275,50.461 v1(75.275,51.672) v1(75.275,55.101) ; v2@79.598,77.937 84.601,77.937 87.257,80.593 v2(87.257,82.528) ; v1(86.837,90.731) 88.229,90.731 89.793,89.168 v1(90.833,89.168) ; v1(90.281,92.762) 90.833,92.211 v1(90.833,89.168) ; v2@90.439,82.528 v2(90.457,82.546) 90.457,85.833 91.645,87.022 91.645,88.355 v1(90.833,89.168)
  Bottom Layer w1: J26.2@38.55,2.997 38.55,8.381 62.558,32.39 v2@94.249,32.39 ; 75.848,49.889 92.797,49.889 v2(94.374,48.312) ; v2@87.257,82.528 v2(88.867,82.528) v2@90.439,82.528 ; v2(90.457,82.546) 101.327,82.546 v2(104.421,79.453) 106.127,77.747 106.127,75.229 v2(102.766,71.868) 98.443,71.868 97.232,70.656 v1(97.232,66.329) v1@97.232,63.114 ; v2(94.349,32.39) v2(94.349,34.316) ; v2(94.377,47.15) 94.374,47.153 v2(94.374,48.312) ; v1@97.232,63.108 v1(97.232,60.827) v1(97.232,59.027) v1(97.232,57.227) 97.232,51.17 v2(94.374,48.312)
VCC_P3V3: C60.2 C61.1 C63.1 J2.20@131,22.809 J6.59 J6.61 J26.1@36.01,2.997 R88.1 R89.1 R90.1 R91.1 R92.2 R96.1 TP67.1 U10.8 U11.8 U13.5 | length 285.8
  Top Layer w0.25: 74.73,52.421 75.104,52.421 75.23,52.547 J6.61@75.23,53.525 ; R96.1@104.484,28.017 104.584,27.917 U13.5@104.584,26.367
  Top Layer w0.3: v2(71.939,47.747) 71.939,49.435 74.73,52.226 74.73,52.421 J6.59@74.73,53.525 ; U10.8@89.917,86.647 89.999,86.566 C60.2@91.507,86.566 ; U13.5@104.657,26.367 106.509,26.367 C63.1@106.584,26.442
  Top Layer w0.5: J26.1@36.01,2.997 36.01,4.421 41.199,9.609 v3(44.393,9.609) ; v2(85.22,43.55) 85.22,34.276 v2(89.736,29.76) ; v2(91.477,85.543) 91.507,85.572 C60.2@91.507,86.566 ; C63.1@106.584,26.442 v2(108.109,26.442) ; v2(112.441,37.792) 112.441,31.594 113.294,30.74 R88.1@114.345,30.74 v2(114.345,29.807) ; v2(112.456,40.063) 113.284,40.891 113.284,42.156 ; U11.8@114.395,40.478 114.395,42.69 C61.1@114.445,42.74 113.868,42.74 ; v2(117.035,29.8) R89.1@117.035,30.73 ; R90.1@118.345,43.89 R92.2@115.745,43.89 115.745,45.307 115.307,45.745 114.072,45.745 113.284,44.956 113.284,43.325 ; 113.284,42.156 113.868,42.74 ; 113.284,42.156 113.284,43.325 ; 113.284,43.325 113.868,42.74
  Bottom Layer w0.5: v3(44.393,9.609) 61.225,26.442 86.419,26.442 v2(89.736,29.76) 93.054,26.442 v2(108.109,26.442) 111.474,29.807 v2(114.345,29.807) 117.028,29.807 v2(117.035,29.8) 118.317,29.8 126.947,21.17 129.361,21.17 J2.20@131,22.809 133.193,25.002 133.193,66.141 123.961,75.373 113.826,75.373 104.519,84.68 104.422,84.68 104.411,84.67 95.273,84.67 94.399,85.543 v2(91.477,85.543) ; v2(71.939,47.747) 71.939,45.149 73.538,43.55 v2(85.22,43.55) ; v2(112.441,37.792) 112.441,40.048 v2(112.456,40.063)
  other v1: 99.453,26.431
VCC_P5V0: C64.1 J18.3@128.46,58.369 J26.3@41.09,2.997 Q3.2 R95.2 R97.2 TP64.1 U13.1 U13.3 U14.7 U17.5 | length 160.4
  Top Layer w0.25: U13.1@103.084,23.567 103.084,22.764 103.182,22.665 103.846,22.665 ; C64.1@103.982,21.667 104.084,21.769 104.084,22.428 ; 104.084,23.112 104.084,22.903 ; U13.3@104.084,23.567 104.084,22.903 ; 103.846,22.665 104.084,22.428 ; 103.846,22.665 104.084,22.665 ; 103.846,22.665 104.084,22.903 ; 104.084,22.428 104.084,22.665 ; 104.084,22.665 104.084,22.903
  Top Layer w0.3: U14.7@106.034,17.742 107.769,17.742 108.084,18.057 R95.2@108.084,20.842 ; Q3.2@115.062,22.549 115.062,23.315 115.475,23.728 R97.2@115.475,24.267 115.475,25.846 TP64.1@115.488,25.858
  Top Layer w0.5: C64.1@103.982,21.667 105.584,21.667 106.409,20.842 R95.2@108.084,20.842 108.084,21.852 108.512,22.281 112.174,22.281 ; 112.775,22.4 112.775,22.882 ; U17.5@112.775,24.151 112.775,22.99 ; Q3.2@115.062,22.549 114.793,22.281 113.484,22.281 ; TP64.1@115.488,25.858 119.783,25.858 124.619,21.023 132.105,21.023 132.927,21.844 132.927,50.334 128.46,54.801 J18.3@128.46,58.369 ; 112.174,22.281 112.775,22.882 ; 112.174,22.281 113.484,22.281 ; 112.775,22.882 112.775,22.99 ; 112.775,22.99 113.484,22.281
  Bottom Layer w0.5: J26.3@41.09,2.997 61.048,22.955 103.832,22.955 v2(105.112,21.674)
VCC_P/2: R44.1 R45.1 R50.1 R55.2 TP15.1 | length 108.8
  Top Layer w0.5: v2(27.317,77.372) 27.337,77.392 R45.1@27.337,79.198 ; v2(69.221,77.519) R44.1@69.221,79.142 ; v2(88.797,76.92) 89.577,76.141 89.577,73.278 88.994,72.695 R55.2@88.01,72.695 88.049,72.655 88.049,71.588 TP15.1@88.935,70.702 ; v2(104.977,76.909) 110.517,76.909 111.052,77.444 R50.1@111.052,79.117
  Bottom Layer w0.5: v2(27.317,77.372) 28.181,76.508 45.508,76.508 50.36,81.36 55.985,81.36 60.948,76.396 68.098,76.396 v2(69.221,77.519) 69.82,76.92 81.044,76.92 ; 84.645,76.92 81.044,76.92 ; v2(104.977,76.909) 103.301,76.909 99.911,80.299 92.176,80.299 v2(88.797,76.92) 81.044,76.92
VCC_TARGET_P: J18.4@131,58.369 R102.1 R104.2 R105.1 | length 70.3
  Top Layer w0.5: v2(95.532,32.39) 95.549,32.407 R105.1@95.549,33.353 96.495,33.353 v2(96.512,33.336) ; R104.2@109.131,25.428 v1(109.131,26.23) 109.131,28.882 109.928,29.679 R102.1@110.867,29.679 110.867,37.739 v3(110.877,37.75)
  Bottom Layer w0.5: v2(95.532,32.39) 95.566,32.39 v2(96.512,33.336) 98.993,30.855 108.752,30.855 109.9,29.707 v3(109.9,29.7) ; 110.877,39.722 v3(110.877,37.75) 110.877,44.199 115.882,49.204 128.727,49.204 131,51.477 J18.4@131,58.369
VCC_TARGET_USB_P5V0: C55.1 C66.1 J6.8 L6.2 R99.2 TP66.1 U14.6 U17.1 | length 108.9
  Top Layer w0.25: J6.8@59.98,45.975 59.98,39.007 75.913,23.075 88.056,23.075 99.791,11.34 103.443,11.34 104.149,10.634 v3(111.576,10.634)
  Top Layer w0.3: C66.1@103.934,18.492 104.034,18.392 U14.6@106.034,18.392
  Top Layer w0.5: v2(101.587,18.442) R99.2@102.634,18.442 102.684,18.492 C66.1@103.934,18.492 ; v3(111.576,10.634) 112.914,9.295 C55.1@112.914,7.547 113.889,7.547 L6.2@114.389,7.047 ; U17.1@112.775,26.601 v2(113.82,26.601)
  Bottom Layer w0.5: v2(101.587,18.442) 106.954,18.442 ; 107.352,19.236 107.352,18.841 ; v3(111.576,10.634) 107.352,14.858 107.352,18.044 ; v2(113.82,26.601) 113.057,26.601 107.352,20.896 107.352,18.841 ; 106.954,18.442 107.352,18.841 ; 106.954,18.442 107.352,18.044 ; 107.352,18.044 107.352,18.841
VCC_X_EXT_P5V0: J18.1@128.46,60.909 SW1.3 | length 195.3
  Top Layer w0.5: v2(126.57,9.24) 133.755,16.425 133.755,62.325 132.775,63.305 129.117,63.305 128.46,62.648 J18.1@128.46,60.909
  Bottom Layer w0.5: SW1.3@12.36,6 17.219,1.141 44.365,1.141 58.021,14.797 79.484,14.797 91.113,3.168 124.442,3.168 126.06,4.786 126.06,8.73 v2(126.57,9.24)
VDC_DRIVER: C23.1 C25.1 C26.1 D7.1 F2.1 R33.2 R62.2 R119.2 R120.2 R123.2 TP38.1 U5.5 | length 75.6
  Top Layer w0.5: R123.2@7.85,21.5 8.82,21.5 9.505,22.186 9.505,23.427 10.016,23.938 R62.2@10.016,24.764 11.239,24.764 12.152,25.677 12.879,25.677 ; U5.5@11.325,18.655 11.325,20.868 C23.1@11.595,21.137 12.874,21.137 13.359,21.621 13.359,25.197 ; 14.113,25.677 13.838,25.677 ; D7.1@27.066,23.836 D7.1@26.865,24.037 ; R33.2@28.85,17.85 28.855,17.846 31.726,17.846 32.167,17.404 32.167,15.267 R120.2@29.6,12.7 ; R119.2@30.5,17.85 30.5,19.424 29.052,20.872 C26.1@29.052,23.918 28.933,24.037 D7.1@26.865,24.037 ; 12.879,25.677 13.337,25.677 ; 12.879,25.677 13.359,25.197 ; 13.337,25.677 13.838,25.677 ; 13.337,25.677 13.359,25.655 13.359,25.197 ; 13.359,25.197 13.838,25.677 ; 13.838,25.677 25.55,25.677 26.865,24.362 D7.1@26.865,24.037
  Top Layer w1: F2.1@16.9,30.7 17,30.6 C25.1@20.6,30.6 20.6,31.967 21.858,33.225 29.076,33.225 29.883,32.418 TP38.1@29.883,27.173 29.052,26.342 C26.1@29.052,23.918
VDC_MOTOR: C3.1 C8.1 C13.1 C18.1 C20.1 F1.2 M1.3 M3.3 M5.3 R2.2 R12.2 R22.2 R79.1 TP27.1 | length 1
  Top Layer w0.2: R79.1@71.94,62.977 v2(71.94,64.006)
  other v1: 28.281,38.897 34.281,38.897 40.281,38.897 46.281,38.897 28.281,40.897 34.281,40.897 40.281,40.897 46.281,40.897 28.281,42.897 34.281,42.897 40.281,42.897 46.281,42.897 28.281,44.897 34.281,44.897 40.281,44.897 46.281,44.897 28.281,46.897 34.281,46.897 40.281,46.897 46.281,46.897 28.281,48.897 34.281,48.897 40.281,48.897 46.281,48.897 28.281,50.897 34.281,50.897 40.281,50.897 46.281,50.897 43.451,100.028 45.451,100.028 47.451,100.028 49.451,100.028 51.451,100.028 53.451,100.028 85.451,100.028 87.451,100.028 89.451,100.028 91.451,100.028 93.451,100.028 95.451,100.028 1.366,100.416 3.366,100.416 5.366,100.416 7.366,100.416 9.366,100.416 11.366,100.416 43.451,102.028 45.451,102.028 47.451,102.028 49.451,102.028 51.451,102.028 53.451,102.028 85.451,102.028 87.451,102.028 89.451,102.028 91.451,102.028 93.451,102.028 95.451,102.028 1.366,102.416 3.366,102.416 5.366,102.416 7.366,102.416 9.366,102.416 11.366,102.416 43.451,104.028 45.451,104.028 47.451,104.028 49.451,104.028 51.451,104.028 53.451,104.028 85.451,104.028 87.451,104.028 89.451,104.028 91.451,104.028 93.451,104.028 95.451,104.028 1.366,104.416 3.366,104.416 5.366,104.416 7.366,104.416 9.366,104.416 11.366,104.416 43.451,106.028 45.451,106.028 47.451,106.028 49.451,106.028 51.451,106.028 53.451,106.028 85.451,106.028 87.451,106.028 89.451,106.028 91.451,106.028 93.451,106.028 95.451,106.028 1.366,106.416 3.366,106.416 5.366,106.416 7.366,106.416 9.366,106.416 11.366,106.416 43.451,108.028 45.451,108.028 47.451,108.028 49.451,108.028 51.451,108.028 53.451,108.028 85.451,108.028 87.451,108.028 89.451,108.028 91.451,108.028 93.451,108.028 95.451,108.028 1.366,108.416 3.366,108.416 5.366,108.416 7.366,108.416 9.366,108.416 11.366,108.416 43.451,110.028 45.451,110.028 47.451,110.028 49.451,110.028 51.451,110.028 53.451,110.028 85.451,110.028 87.451,110.028 89.451,110.028 91.451,110.028 93.451,110.028 95.451,110.028 1.366,110.416 3.366,110.416 5.366,110.416 7.366,110.416 9.366,110.416 11.366,110.416
VSHUNT_ADC: C33.2 J6.39 R51.2 TP16.1 U7.1 | length 43.4
  Top Layer w0.2: R51.2@61.04,84.283 61.285,84.038 C33.2@61.285,82.431 61.285,81.945 61.675,81.555 65.085,81.555 66.192,80.447 U7.1@67.125,80.447 67.11,80.432 TP16.1@67.11,77.658 71.649,73.119 71.649,66.88 v1(72.541,65.988) ; J6.39@69.73,53.525 69.73,52.376 v1(70.096,52.011)
  Bottom Layer w0.2: v1(70.096,52.011) 68.83,53.276 68.83,55.5 69.33,56 69.33,56.012 71.011,57.692 71.011,58.127 70.949,58.188 70.949,64.397 v1(72.541,65.988)
W_EMF: C16.2 CONN2.3 D6.1 M5.1 M6.3 R27.1 R28.2 R29.2 R74.1 TP54.1 | length 17.7
  Top Layer w0.2: R28.2@100.794,88.368 100.794,89.391 101.082,89.68 103.5,89.68 106.009,92.188 D6.1@106.237,92.188 106.237,90.387 104.5,88.65 102.876,88.65 R74.1@102.594,88.368
  Top Layer w2: 106.071,95.876 106.237,95.709 D6.1@106.237,92.188
  other v1: 102.6,100.208 104.6,100.208 106.6,100.208 108.6,100.208 110.6,100.208 102.6,102.208 104.6,102.208 106.6,102.208 108.6,102.208 110.6,102.208 102.6,104.208 104.6,104.208 106.6,104.208 108.6,104.208 110.6,104.208 102.6,106.208 104.6,106.208 106.6,106.208 108.6,106.208 110.6,106.208 102.6,108.208 104.6,108.208 106.6,108.208 108.6,108.208 110.6,108.208 102.6,110.208 104.6,110.208 106.6,110.208 108.6,110.208 110.6,110.208 102.6,112.208 104.6,112.208 106.6,112.208 108.6,112.208 110.6,112.208
WSHUNT_ADC: C37.2 J6.40 R53.2 TP19.1 U9.1 | length 67.7
  Top Layer w0.2: v1(69.677,48.35) 69.677,48.3 69.98,47.996 J6.40@69.98,45.975 ; v1(80.484,58.058) 95.345,72.919 99.809,72.919 105.216,78.326 TP19.1@108.91,78.326 108.886,78.35 U9.1@108.886,80.456 108.114,80.456 107.044,81.525 103.249,81.525 102.961,81.814 C37.2@102.961,82.409 102.961,83.882 R53.2@102.701,84.141
  Bottom Layer w0.2: v1(69.677,48.35) 70.217,48.35 73.173,51.306 73.173,55.627 75.059,57.512 79.939,57.512 v1(80.484,58.058)
pads on no net: J2.1@128.46,45.669 J2.2@131,45.669 J2.3@128.46,43.129 J2.4@131,43.129 J2.5@128.46,40.589 J2.6@131,40.589 J2.7@128.46,38.049 J2.8@131,38.049 J2.9@128.46,35.509 J2.10@131,35.509 J2.11@128.46,32.969 J2.12@131,32.969 J2.13@128.46,30.429 J2.14@131,30.429 J2.15@128.46,27.889 J2.16@131,27.889 J2.17@128.46,25.349 J2.18@131,25.349 J2.19@128.46,22.809 J2.20@131,22.809 J4.4 J4.6@98.43,1.3 J4.7@105.63,1.3 J4.8@99.805,4.425 J4.9@104.255,4.425 J5.6@116.53,1.3 J5.7@123.73,1.3 J5.8@117.905,4.425 J5.9@122.355,4.425 J6.0 J6.2 J6.5 J6.60 J7.4 J8.4 J9.4 J10.4 J11.4 J12.4 J13.4 J14.4 J18.1@128.46,60.909 J18.2@131,60.909 J18.3@128.46,58.369 J18.4@131,58.369 J19.4 J20.4 J21.4 J23.4 J24.4 J25.4 J26.1@36.01,2.997 J26.2@38.55,2.997 J26.3@41.09,2.997 TP22.3 TP24.3 U1.5 U1.6 U1.9 U1.10 U5.6 U5.7 U10.0 U12.1 U12.2 U12.3 U12.6 U12.7 U13.0 U13.2 U13.4 U13.6 U16.5 U16.6 U16.9 U16.10

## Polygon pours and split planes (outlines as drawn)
GND_E on Top Layer "GND_E" (solid, remove dead copper, pour order 310): 0.612,59.949 16.093,59.949 16.093,64.076 26.131,64.076 26.131,66.497 26.131,72.779 25.107,72.779 0.612,72.779 0.612,59.949
GND on Top Layer "GND" (solid, remove dead copper, pour order 309): 22.722,54.435 22.722,62.997 27.131,62.997 27.131,72.758 50.317,72.758 50.317,58.462 50.317,54.435
NetC17_2 on Top Layer "R" (solid, remove dead copper, pour order 287): 112.753,104.952 116.68,104.95 116.68,110.562 126.085,110.562 126.085,95.297 113.434,95.297 113.434,99.868 112.753,99.868
W_EMF on Top Layer "W_EMF" (solid, remove dead copper, pour order 281): 98.25,104.684 98.25,99.685 104.432,99.685 104.432,94.835 107.837,94.835 107.837,100.092 111.785,100.092 111.785,124 70.8,124 70.8,111.562 101.826,111.562 101.826,104.674
NetC7_2 on Top Layer "R" (solid, remove dead copper, pour order 289): 28.742,104.678 32.68,104.678 32.68,110.562 42.085,110.562 42.085,95.297 29.434,95.297 29.434,99.868 28.753,99.868
VDC_MOTOR on Top Layer "VDC" (solid, remove dead copper, pour order 291): 97.285,98.685 98.862,98.685 98.862,94.837 85.085,94.837 85.085,110.562 97.285,110.562
VDC_MOTOR on Top Layer "VDC" (solid, remove dead copper, pour order 293): 55.285,98.685 56.862,98.685 56.862,94.981 43.085,94.981 43.085,110.562 55.285,110.562
VDC_MOTOR on Top Layer "VDC" (solid, remove dead copper, pour order 275): 13.285,110.95 1,110.95 1,95.131 15.057,95.131 15.04,98.431 13.285,98.431
U_EMF on Top Layer "U_EMF" (solid, remove dead copper, pour order 277): 14.235,99.881 20.385,99.881 20.385,94.835 24.035,94.835 24.035,99.78 27.785,99.78 27.785,111.562 58.488,111.562 58.488,124 17.785,124 17.785,104.73 14.235,104.73
GND on Top Layer "p" (solid, remove dead copper, pour order 304): 93.815,90.893 93.815,93.493 96.461,93.493 97.072,93.493 97.072,90.743 93.815,90.743
GND on Top Layer "p" (solid, remove dead copper, pour order 305): 51.898,90.904 51.898,93.504 54.545,93.504 55.155,93.504 55.155,90.754 51.898,90.754
GND on Top Layer "p" (solid, remove dead copper, pour order 306): 9.872,90.699 9.872,93.299 12.518,93.299 13.129,93.299 13.129,90.549 9.872,90.549
NetCONN1_1 on Top Layer "P" (solid, remove dead copper, pour order 301): 1,54.593 20.265,54.593 20.265,37.35 1,37.35
VDC_MOTOR on Top Layer "p" (solid, remove dead copper, pour order 302): 50.317,52.435 50.317,37.35 22.722,37.35 22.722,52.435
NetC12_2 on Top Layer "R" (solid, remove dead copper, pour order 283): 70.74,105.62 74.68,105.62 74.68,110.562 84.085,110.562 84.085,95.297 71.885,95.297 71.885,99.868 70.753,99.868
GND on Top Layer "GND" (solid, remove dead copper, pour order 300): 84.085,90.109 84.085,79.322 71.195,79.322 71.195,90.109
GND on Top Layer "GND" (solid, remove dead copper, pour order 298): 42.085,90.109 42.085,79.322 29.195,79.322 29.195,90.109
GND on Top Layer "GND" (solid, remove dead copper, pour order 296): 126.085,90.109 126.085,79.322 113.195,79.322 113.195,90.109
V_EMF on Top Layer "V_EMF" (solid, remove dead copper, pour order 279): 56.214,104.678 56.214,99.685 62.605,99.685 62.605,94.835 66.306,94.835 66.306,99.623 69.8,99.623 69.8,124 59.488,124 59.488,104.68
GND_E on Bottom Layer "GND_E" (solid, remove dead copper, pour order 286): 0.612,58.487 26.131,58.487 26.131,63.247 26.131,72.779 25.107,72.779 0.612,72.779 0.612,58.487
VDC_MOTOR on Bottom Layer "p" (solid, remove dead copper, pour order 303): 50.317,52.435 50.317,37.35 22.722,37.35 22.722,52.435
NetCONN1_1 on Bottom Layer "P" (solid, remove dead copper, pour order 294): 0.612,54.593 20.265,54.593 20.265,37.35 0.612,37.35
GND on Bottom Layer "GND" (solid, remove dead copper, pour order 308): -13,91.15 136.588,91.15 136.588,-3.942 -13,-3.942
NetC17_2 on Bottom Layer "R" (solid, remove dead copper, pour order 284): 113.434,104.722 116.68,104.722 116.68,110.562 126.085,110.562 126.085,92.522 113.434,92.522
NetC12_2 on Bottom Layer "R" (solid, remove dead copper, pour order 282): 71.872,104.722 74.68,104.722 74.68,110.562 84.085,110.562 84.085,92.522 71.885,92.522 71.885,97.924
VDC_MOTOR on Bottom Layer "VDC" (solid, remove dead copper, pour order 290): 97.285,94.837 85.085,94.837 85.085,110.562 97.285,110.562
VDC_MOTOR on Bottom Layer "VDC" (solid, remove dead copper, pour order 292): 55.285,94.981 43.085,94.981 43.085,110.562 55.285,110.562
VDC_MOTOR on Bottom Layer "VDC" (solid, remove dead copper, pour order 273): 13.285,110.95 1,110.95 1,95.131 13.301,95.131 13.285,98.431
V_EMF on Bottom Layer "V_EMF" (solid, remove dead copper, pour order 278): 58.065,104.679 58.065,99.685 62.605,99.685 62.605,94.835 66.306,94.835 66.306,99.623 69.8,99.623 69.8,111.562 69.8,124 59.488,124 59.488,104.68
NetC7_2 on Bottom Layer "R" (solid, remove dead copper, pour order 288): 29.421,104.722 32.68,104.722 32.68,110.562 42.085,110.562 42.085,92.522 29.434,92.522 29.434,97.924
U_EMF on Bottom Layer "U_EMF" (solid, remove dead copper, pour order 276): 16.26,101.43 20.268,101.43 20.268,94.835 24.035,94.835 24.035,99.78 27.785,99.78 27.785,111.562 58.488,111.562 58.488,124 17.785,124 17.785,104.73 16.26,104.73
GND on Bottom Layer "GND" (solid, remove dead copper, pour order 299): 84.085,91.522 84.085,79.322 71.195,79.322 71.195,91.522
GND on Bottom Layer "GND" (solid, remove dead copper, pour order 297): 42.085,91.522 42.085,79.322 29.195,79.322 29.195,91.522
GND on Bottom Layer "GND" (solid, remove dead copper, pour order 295): 126.085,91.522 126.085,79.322 113.195,79.322 113.195,91.522
W_EMF on Bottom Layer "W_EMF" (solid, remove dead copper, pour order 280): 98.25,104.684 98.25,99.685 104.432,99.685 104.432,94.835 107.837,94.835 107.837,100.092 111.785,100.092 111.785,124 70.8,124 70.8,111.562 101.826,111.562 101.826,104.674
GND_E on GND "GND_E" (solid, remove dead copper, pour order 285): 0.612,58.487 26.131,58.487 26.131,63.247 26.131,72.779 25.107,72.779 0.612,72.779 0.612,58.487
GND on GND "GND" (solid, remove dead copper, pour order 307): 0,0 0,124.415 135,124.415 135,0
VDC_MOTOR on PWR/Signal "p" (solid, remove dead copper, pour order 274): 71.609,-0.143 71.609,46.845 136.388,46.828 136.388,134.048 -5.239,134.048 -5.239,-1.5 54.6,-1.5
VCC_P on PWR/Signal "P3V3" (solid, remove dead copper, pour order 272): 135.075,-0.978 135.075,45.835 72.609,45.835 72.609,-0.978

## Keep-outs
Keep-Out Layer:
  lines w0.2: 1.27,0 cw(c1.27,1.27) 0,1.27 0,1.35 0,123.73 cw(c1.27,123.73) 1.27,125 133.73,125 cw(c133.73,123.73) 135,123.73 135,1.27 cw(c133.73,1.27) 133.73,0 69.75,0 69.25,0 cw(c69.25,0.5) 68.75,0.5 68.75,6.14 ccw(c67.5,6.14) 67.5,7.39 ; 1.289,-0.003 1.677,-0.003 ; 1.483,0 65.75,0 ccw(c65.75,0.5) 66.25,0.5 66.25,6.15 cw(c67.5,6.15) 67.5,7.4

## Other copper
Bottom Layer:
  pour cut-out: 42.36,1.517 34.74,1.517 34.74,4.477 42.36,4.477
  pour cut-out: 20.718,36.841 26.631,36.841 26.631,58.01 20.718,58.01

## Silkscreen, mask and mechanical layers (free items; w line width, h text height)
Top Overlay:
  circle w0.254: c5,5 r3.1
  circle w0.254: c5,120 r3.1
  circle w0.254: c130,120 r3.1
  circle w0.254: c130,5 r3.1
  circle w0.2: c83.235,67.162 r0.85
  lines w0.15: 16.078,85.716 19.565,85.716 19.565,89.892
  lines w0.2: 36.183,4.805 36.183,5.397 38.662,5.397 ; 38.662,4.83 38.662,5.397 ; 41.14,4.805 41.14,5.397 38.662,5.397 ; 67.789,40.179 67.772,40.179 ; 105.222,28.815 105.222,28.832 ; 67.772,40.179 65.245,37.652 66.775,37.652 66.775,32.584 68.77,32.584 68.77,37.652 70.299,37.652 67.772,40.179
  text "H" at 89.003,118.581 h10
  text "U" at 48.568,117.887 h3
  text "W" at 79.212,117.887 h3
  text "ATBLDC24V" at 96.287,113.345 h4
  text "GND" at 124.066,112.947 h1.4
  text "V" at 63.793,110.061 h3
  text "ChZ" at 124.184,109.31 h1.52
  text "ChA" at 124.106,105.798 h1.52
  text "ENCODER" at 123.302,102.867 h1.52 r90
  text "5V" at 125.142,102.335 h1.52
  text "ChB" at 124.131,98.901 h1.52
  text "H3" at 124.543,91.628 h1.52
  text "1" at 90.22,90.634 h1.52
  text "H2" at 124.804,87.775 h1.52
  text "U-BE" at 22.505,85.932 h1.52
  text "W-BE" at 106.18,85.926 h1.52
  text "V-BE" at 63.18,85.776 h1.52
  text "H1" at 124.76,84.935 h1.52
  text "GND" at 123.915,81.178 h1.4
  text "5V" at 124.862,77.59 h1.52
  text "W-SH" at 107.33,75.981 h1.52
  text "U-SH" at 23.767,75.963 h1.52
  text "V-SH" at 65.71,75.231 h1.52
  text "HALL" at 129.148,74.135 h1.52
  text "UH" at 61.898,71.842 h1.52
  text "UL" at 64.438,71.842 h1.52
  text "VH" at 66.978,71.842 h1.52
  text "VL" at 69.518,71.842 h1.52
  text "WH" at 71.87,71.85 h1.52
  text "WL" at 74.598,71.842 h1.52
  text "GND" at 39.025,71.072 h1.52
  text "H1" at 125.35,70.648 h1.52
  text "H1" at 92.301,70.448 h1.52
  text "1" at 101.681,69.121 h1.52
  text "H2" at 125.35,68.148 h1.52
  text "H2" at 92.301,67.948 h1.52
  text "H3" at 125.35,65.648 h1.52
  text "H3" at 92.301,65.448 h1.52
  text "-" at 4.427,65.331 h9
  text "VCC-MCU" at 80.287,64.985 h1.52
  text "M-VDC" at 62.42,64.75 h1.52
  text "PWR" at 128.206,64.118 h1.52
  text "H-OE" at 89.04,63.473 h1.52
  text "1" at 128.028,62.502 h1.52
  text "E-B" at 124.989,61.308 h1.52
  text "E-B" at 91.903,61.277 h1.52
  text "1" at 101.559,60.45 h1.52
  text "E-A" at 91.903,58.777 h1.52
  text "E-A" at 125.056,58.705 h1.52
  text "E-Z" at 125.14,56.118 h1.52
  text "3" at 127.927,55.653 h1.52
  text "E-EN" at 88.962,55.197 h1.52
  text "E-Z" at 94.62,54.3 h1.52
  text "EXT1" at 128.206,48.32 h1.52
  text "1" at 125.45,45.187 h1.52
  text "+" at 4.485,45.156 h5
  text "(12-24VDC)" at 1.79,44.35 h1.52
  text "3" at 125.45,42.647 h1.52
  text "5" at 125.45,40.107 h1.52
  text "GND" at 102.285,39.762 h1.52
  text "7" at 125.45,37.567 h1.52
  text "9" at 125.45,35.027 h1.52
  text "11" at 125.45,32.487 h1.52
  text "13" at 125.45,29.947 h1.52
  text "MCU CARD" at 61.162,29.498 h3
  text "15" at 125.45,27.407 h1.52
  text "P5V0" at 117.166,25.417 h1.52
  text "17" at 125.45,24.867 h1.52
  text "OV-LED" at 1.465,24.781 h1.52 r90
  text "P3V3" at 98.037,24.225 h1.52
  text "1" at 101.635,22.662 h1.2
  text "19" at 125.45,22.4 h1.52
  text "OC-LED" at 1.465,16.568 h1.52 r90
  text "EXT_P5V0" at 123.934,14.545 h1.52
  text "PWR-LED" at 1.465,8.101 h1.52 r90
  text "3V3" at 35.743,5.85 h1.52
  text "5V0" at 39.725,5.822 h1.52
  text "TARGET" at 109.032,1.965 h1.52
  text "EDBG" at 91.326,1.943 h1.52
  text "OC-RST" at 33.82,1.27 h1.52 r90
  text "USB/X5V" at 9.431,0.86 h1.52 r90
  text "MOT-5V" at 21.44,0.635 h1.52 r90
Bottom Overlay:
  circle w0.254: c130,5 r3.1
  circle w0.254: c5,5 r3.1
  circle w0.254: c5,120 r3.1
  circle w0.254: c130,120 r3.1
  text "EXT_P5V" at 121.585,60.584 h1.52
  text "GND" at 126.643,60.552 h1.52
  text "5V" at 121.585,57.858 h1.52
  text "VCC_P" at 126.643,57.839 h1.52
  text "ID" at 118.935,45.293 h1.52
  text "GND" at 126.565,45.293 h1.52
  text "ADC(+)" at 118.935,42.712 h1.52
  text "ADC(-)" at 126.565,42.712 h1.52
  text "GPIO" at 118.935,40.264 h1.52
  text "GPIO" at 126.565,40.264 h1.52
  text "PWM(+)" at 118.935,37.702 h1.52
  text "PWM(-)" at 126.565,37.702 h1.52
  text "IRQ/GPIO" at 118.935,35.224 h1.52
  text "GPIO" at 126.565,35.224 h1.52
  text "TWI_SDA" at 118.935,32.559 h1.52
  text "TWI_SCL" at 126.565,32.559 h1.52
  text "UART_RX" at 118.935,29.99 h1.52
  text "UART_TX" at 126.565,29.99 h1.52
  text "SPI_SS" at 118.935,27.491 h1.52
  text "SPI_MOSI" at 126.565,27.491 h1.52
  text "SPI_MISO" at 118.935,24.884 h1.52
  text "SPI_SCK" at 126.565,24.884 h1.52
  text "GND" at 118.935,22.438 h1.52
  text "VCC" at 126.565,22.438 h1.52
  text "Atmel Corp © 2015" at 91.742,18.203 h1.52
  text "A08-2306 Rev 2" at 92.276,11.57 h2
  text "t" at 84.166,3.598 h7
  text "c" at 91.864,3.241 h5
  text "f" at 98.473,3.175 h5
  text "p" at 76.898,2.593 h7
Mechanical 1:
  lines w0.2: 67.5,7.39 cw(c67.5,6.14) 68.75,6.14 68.75,0.5 ccw(c69.25,0.5) 69.25,0 69.75,0 133.73,0 ccw(c133.73,1.27) 135,1.27 135,123.73 ccw(c133.73,123.73) 133.73,125 1.27,125 ccw(c1.27,123.73) 0,123.73 0,1.35 0,1.27 ccw(c1.27,1.27) 1.27,0 65.75,0 ccw(c65.75,0.5) 66.25,0.5 66.25,6.15 cw(c67.5,6.15) 67.5,7.4
Mechanical 4:
  drawing of 187 lines, arcs and shapes, not listed
  text "SOLDER LEVEL" at -86.562,97.024 h1.78
  text "( SEE NOTE 2A )" at -63.575,97.024 h1.78
  text "COPPER PLATE" at -86.562,94.484 h1.78
  text "70 um" at -61.289,93.214 h1.78
  text "LAYER 1" at -119.836,91.944 h1.78
  text "COPPER FOIL" at -86.562,91.944 h1.78
  text "}" at -64.845,91.817 h4.44
  text "Prepregs" at -86.448,88.912 h1.78
  text "( SEE NOTE 1A )" at -42.633,88.912 h1.78
  text "118 um" at -71.974,88.601 h1.78
  text "COPPER FOIL" at -86.573,84.41 h1.78
  text "LAYER 2" at -119.836,84.406 h1.78
  text "70 um" at -65.276,84.38 h1.78
  text "CORE" at -85.862,71.513 h1.78
  text "1200 um" at -71.511,71.513 h1.78
  text "1.6 mm +/- 0.15" at -129.374,71.101 h1.78
  text "LAYER 3" at -119.736,58.135 h1.78
  text "COPPER FOIL" at -86.448,58.089 h1.78
  text "70 um" at -65.176,57.907 h1.78
  text "Prepregs" at -86.348,54.169 h1.78
  text "118 um" at -71.997,54.169 h1.78
  text "LAYER 4" at -119.836,50.034 h1.78
  text "COPPER FOIL" at -86.562,50.034 h1.78
  text "70 um" at -61.289,48.764 h1.78
  text "COPPER PLATE" at -86.562,47.494 h1.78
  text "}" at -64.845,47.367 h4.44
  text "SOLDER LEVEL" at -86.562,44.954 h1.78
  text "( SEE NOTE 2A )" at -63.575,44.954 h1.78
  text "NOTE  1A:  DIELECTRIC FR4" at -113.564,37.412 h1.78
  text "2A:  SURFACE PROTECTION: Chemical Gold" at -104.826,34.876 h1.78
  text "THE BOARD MUST BE RoHS COMPLIANT" at -104.965,29.756 h1.78
  text "DETAIL A ( CROSS-SECTION )" at -113.437,20.902 h3.05
  text "SCALE = NONE" at -94.26,16.33 h1.78

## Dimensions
-0.273,-0.003 to -0.38,125 on Mechanical 4
0,1.27 to 66.25,6.15 on Mechanical 4
135,-0.15 to 68.75,-0.45 on Mechanical 4
0,-0.354 to 135,-0.15 on Mechanical 4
